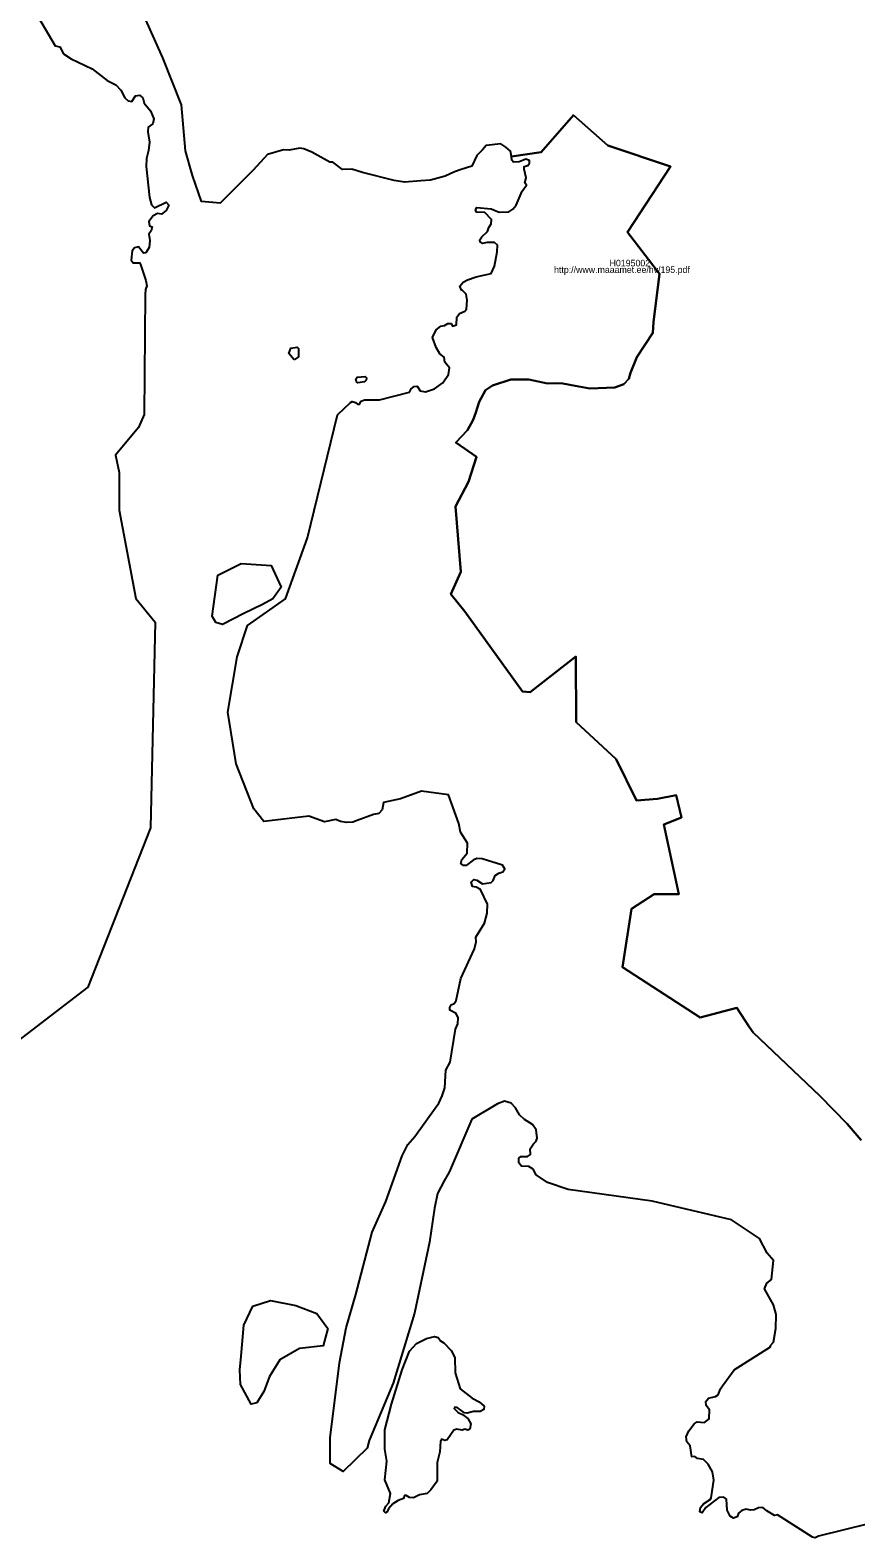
# Model space of a CAD drawing. Extents: x 369010 to 739155, y 6377141 to 6634081.
# Drawn here: x 473944 to 477086, y 6488350 to 6494090 of the extents above; entities that cross this region are included whole.
import ezdxf

# ---------------------------------------------------------------- set-up
doc = ezdxf.new("R2010")
doc.units = 0
for name, color, linetype in [('H_LINK', 7, 'Continuous'), ('H_PIIR', 7, 'Continuous'), ('H_TUNNUS', 7, 'Continuous')]:
    doc.layers.add(name, color=color, linetype=linetype)

msp = doc.modelspace()

# ---------------------------------------------------------------- linework, layer by layer
at = {"layer": 'H_PIIR'}
for points in [[(477105.81, 6489863.6599), (477053.1001, 6489926.8), (476948.82, 6490032.56), (476694.89, 6490274.23), (476679.33, 6490296.0501), (476633.0701, 6490367.9899), (476493.14, 6490331.6599), (476197.2999, 6490523.06), (476232.4499, 6490745.25), (476318.77, 6490800.43), (476411.3899, 6490800.8701), (476354.3301, 6491066.2601), (476422.4101, 6491092.2401), (476402.1901, 6491177.4999), (476330.5199, 6491164.3401), (476250.9799, 6491157.16), (476173.7901, 6491315.3599), (476021.6, 6491455.23), (476019.83, 6491706.0699), (475846.6001, 6491569.67), (475816.77, 6491572.98), (475597.3201, 6491877.66), (475544.2301, 6491943.1199), (475582.14, 6492027.4901), (475562.5499, 6492276.2201), (475611.42, 6492370.95), (475641.97, 6492465.69), (475563.7999, 6492520.34), (475608.2199, 6492567.65), (475629.13, 6492607.3199), (475639.8599, 6492634.9099), (475652.7401, 6492675.06), (475675.8301, 6492719.44), (475702.7499, 6492737.89), (475772.24, 6492760.48), (475840.7099, 6492760.48), (475911.8301, 6492745.3401), (475942.09, 6492746.7), (475970.38, 6492745.6), (476017.03, 6492736.4899), (476073.5, 6492725.46), (476168.17, 6492729.35), (476202.22, 6492741.94), (476221.6101, 6492763.0399), (476227.5, 6492786.31), (476252.8101, 6492845.74), (476312.6699, 6492937.3801), (476314.9799, 6492979.1), (476337.83, 6493162.4601), (476216.68, 6493321.0601), (476380.2801, 6493571.28), (476142.0301, 6493650.73), (476010.69, 6493766.86), (475888.52, 6493626.2901), (475774.6921, 6493608.7703), (475770.8299, 6493629.36), (475753.4, 6493645.4001), (475735.2701, 6493657.25), (475679.35, 6493651.66), (475664.3384, 6493634.0993), (475643.4809, 6493612.6467), (475624.6508, 6493572.1867), (475583.5938, 6493559.8427), (475558.7, 6493551.03), (475522.9239, 6493534.0326), (475467.488, 6493519.7991), (475430.1431, 6493516.6715), (475367.4753, 6493511.8616), (475328.4685, 6493517.8132), (475208.725, 6493548.3742), (475168.275, 6493560.9243), (475132.715, 6493560.2243), (475095.04, 6493587.5199), (475084.58, 6493588.2201), (475014.84, 6493625.88), (474984.86, 6493638.4401), (474969.5201, 6493641.2199), (474929.0699, 6493633.55), (474908.15, 6493634.2499), (474846.5742, 6493616.982), (474792.3345, 6493557.4507), (474666.6572, 6493431.7733), (474595.2195, 6493438.3879), (474560.8236, 6493537.6069), (474534.3653, 6493631.5341), (474519.8131, 6493806.1595), (474448.3755, 6493984.7536), (474357.0941, 6494189.8061)], [(473975.961, 6494138.2034), (474038.8399, 6494030.7401), (474056.7601, 6494027.2699), (474070.6301, 6494000.6699), (474100.1101, 6493981.0199), (474180, 6493943.16), (474237.2199, 6493898.0701), (474269.5899, 6493882.4601), (474288.0899, 6493862.2299), (474303.6901, 6493832.7399), (474316.4101, 6493821.7599), (474330.2801, 6493818.8699), (474344.1601, 6493840.8399), (474359.1801, 6493842.5699), (474371.9, 6493832.7399), (474377.68, 6493812.51), (474401.38, 6493783.03), (474414.67, 6493752.39), (474410.05, 6493733.31), (474393.29, 6493721.17), (474391.55, 6493702.68), (474397.91, 6493663.36), (474394.3801, 6493632.5199), (474385.7001, 6493601.31), (474385.1301, 6493570.67), (474397.8401, 6493453.32), (474404.78, 6493425.5701), (474417.2399, 6493413.53), (474461.2001, 6493436.07), (474471.1001, 6493423.6299), (474460.5699, 6493404.0399), (474443.2899, 6493390.13), (474428.2599, 6493391.71), (474411.4599, 6493383.64), (474395.4301, 6493361.3299), (474397.52, 6493345.98), (474407.28, 6493341.7999), (474404.49, 6493326.46), (474394.7299, 6493313.9), (474399.61, 6493289.49), (474396.12, 6493262.2901), (474383.57, 6493242.77), (474374.51, 6493241.3699), (474355.6801, 6493265.0799), (474340.34, 6493261.5999), (474331.2699, 6493250.44), (474327.78, 6493214.8699), (474336.15, 6493205.1101), (474360.56, 6493205.1101), (474364.7399, 6493193.95), (474383.57, 6493137.24), (474387.76, 6493117.02), (474382.88, 6493103.0701), (474381.7681, 6493083.5003), (474377.5347, 6492627.3577), (474355.3097, 6492577.616), (474268.5262, 6492472.3116), (474281.7554, 6492406.1656), (474281.7554, 6492263.2903), (474345.917, 6491925.9459), (474418.6775, 6491836.6489), (474401.2796, 6491053.1556), (474163.1541, 6490447.2585), (473790.0908, 6490161.508)], [(477231.0565, 6488427.7208), (476942.98, 6488357.15), (476931.13, 6488350.18), (476920.67, 6488352.96), (476787.84, 6488437.3699), (476776.6801, 6488435.2801), (476747.4, 6488452.71), (476732.06, 6488465.96), (476714.62, 6488463.87), (476698.58, 6488456.9), (476684.64, 6488455.5), (476667.9, 6488459.69), (476651.16, 6488454.1099), (476639.3101, 6488444.3399), (476634.43, 6488430.4), (476619.7801, 6488425.52), (476607.23, 6488432.49), (476595.3799, 6488455.5), (476593.98, 6488498.0499), (476582.8201, 6488505.0201), (476564.7, 6488503.63), (476515.1799, 6488465.2701), (476500.54, 6488445.74), (476491.47, 6488449.23), (476494.9599, 6488465.2701), (476505.4199, 6488479.91), (476531.22, 6488495.95), (476535.4099, 6488502.93), (476545.1699, 6488569.88), (476540.29, 6488601.2599), (476524.25, 6488631.2499), (476506.1201, 6488647.9899), (476483.11, 6488652.1801), (476473.34, 6488659.85), (476461.4899, 6488658.4499), (476454.52, 6488701), (476442.6601, 6488716.34), (476439.87, 6488734.47), (476449.63, 6488758.1799), (476470.55, 6488783.99), (476481.7099, 6488792.3601), (476510.3, 6488788.8701), (476527.04, 6488802.8201), (476528.4299, 6488836.99), (476515.8801, 6488854.43), (476514.49, 6488869.0701), (476524.9499, 6488882.3199), (476552.1399, 6488887.9), (476561.21, 6488894.88), (476570.27, 6488917.89), (476578.6399, 6488929.0499), (476622.7493, 6488990.1939), (476761.24, 6489077.07), (476759.8399, 6489081.25), (476772.39, 6489095.1999), (476780.7601, 6489146.81), (476782.8499, 6489200.51), (476772.39, 6489237.48), (476737.53, 6489298.8499), (476747.2901, 6489319.7701), (476764.72, 6489333.72), (476772.2056, 6489405.8832), (476748.1621, 6489434.5361), (476719.0578, 6489490.0987), (476611.9014, 6489560.7426), (476310.2758, 6489632.1802), (475991.1876, 6489676.6303), (475911.8125, 6489703.6179), (475869.5599, 6489732.8101), (475857.71, 6489753.73), (475841.67, 6489764.2), (475813.78, 6489765.5899), (475802.6199, 6489778.14), (475802.6199, 6489796.2801), (475810.99, 6489801.86), (475836.0899, 6489802.5499), (475847.25, 6489809.5299), (475846.5501, 6489831.15), (475858.41, 6489850.68), (475869.5599, 6489860.44), (475873.0499, 6489872.3), (475868.87, 6489903.6801), (475855.62, 6489923.9001), (475824.93, 6489943.4301), (475806.1099, 6489960.87), (475790.76, 6489987.3701), (475774.03, 6490005.5), (475748.23, 6490012.48), (475722.4299, 6490002.7099), (475624.8, 6489944.13), (475538.2201, 6489742.1589), (475518.49, 6489709.98), (475493.77, 6489661.1962), (475482.6574, 6489605.6336), (475463.6074, 6489475.4584), (475406.4573, 6489205.5828), (475324.68, 6488939.59), (475233.5197, 6488721.3317), (475225.8497, 6488691.3417), (475134.9942, 6488602.5962), (475085.7816, 6488632.7588), (475085.7816, 6488731.184), (475120.7067, 6489016.9345), (475146.1068, 6489150.2848), (475182.6193, 6489277.2851), (475244.532, 6489513.5585), (475296.9196, 6489631.0337), (475358.8, 6489804.8299), (475380.4201, 6489848.07), (475407.61, 6489878.7599), (475485.02, 6489986.1601), (475498.83, 6490005.0499), (475511.3801, 6490032.9501), (475521.1401, 6490063.64), (475525.33, 6490130.59), (475542.06, 6490161.28), (475562.29, 6490286.8101), (475571.3501, 6490307.04), (475572.05, 6490330.0501), (475565.0801, 6490346.0899), (475540.6699, 6490359.3399), (475539.97, 6490369.8001), (475546.25, 6490378.87), (475557.4099, 6490384.45), (475565.0801, 6490395.61), (475582.51, 6490480.0001), (475634.1099, 6490592.28), (475640.39, 6490618.78), (475639, 6490637.6101), (475672.98, 6490690.6601), (475682.0399, 6490728.32), (475683.44, 6490763.1899), (475657.64, 6490818.28), (475640.9, 6490827.3501), (475626.95, 6490830.1399), (475622.0699, 6490846.8799), (475631.8299, 6490856.64), (475642.99, 6490853.8499), (475664.61, 6490840.5999), (475697.38, 6490845.48), (475705.7501, 6490852.46), (475713.42, 6490871.2901), (475726.67, 6490880.3599), (475742.7101, 6490885.93), (475749.6801, 6490897.7901), (475741.32, 6490911.0401), (475663.91, 6490935.45), (475642.99, 6490936.8499), (475629.74, 6490930.5699), (475603.24, 6490909.65), (475592.0801, 6490909.65), (475583.02, 6490918.0201), (475586.51, 6490932.66), (475606.73, 6490957.0699), (475607.43, 6490994.7301), (475581.7882, 6491036.415), (475575.4382, 6491069.7525), (475535.7506, 6491179.2903), (475432.5202, 6491193.0773), (475353.1877, 6491163.4152), (475287.8999, 6491149.9001), (475283.72, 6491121.31), (475270.47, 6491108.06), (475250.25, 6491104.57), (475188.1899, 6491081.56), (475171.4499, 6491074.58), (475147.7399, 6491073.1901), (475124.0299, 6491078.07), (475107.2999, 6491085.7399), (475064.2622, 6491076.1026), (475003.937, 6491098.3276), (474832.4867, 6491077.6901), (474794.3866, 6491125.3151), (474727.7115, 6491296.7655), (474695.9614, 6491493.6159), (474730.8865, 6491704.7538), (474770.5741, 6491823.8165), (474915.0369, 6491925.4167), (474999.1745, 6492157.1922), (475113.4748, 6492625.5056), (475162.3301, 6492672.4699), (475168.6101, 6492676.6601), (475181.8601, 6492672.4699), (475189.53, 6492666.2001), (475196.5, 6492666.89), (475203.48, 6492677.36), (475215.3301, 6492682.9401), (475272.5101, 6492682.9401), (475386.87, 6492711.53), (475393.15, 6492724.78), (475404.31, 6492733.1501), (475416.1601, 6492735.24), (475427.32, 6492717.11), (475447.54, 6492713.62), (475482.4099, 6492724.78), (475513.79, 6492747.1), (475535.41, 6492779.8801), (475538.8899, 6492804.98), (475521.46, 6492826.6001), (475519.3699, 6492845.43), (475501.93, 6492857.99), (475487.99, 6492881.7), (475474.74, 6492920.0601), (475488.6799, 6492949.35), (475506.1201, 6492963.2999), (475520.76, 6492966.0899), (475532.6199, 6492973.0599), (475545.17, 6492973.0599), (475550.75, 6492964.0001), (475565.39, 6492968.18), (475567.48, 6492998.17), (475577.94, 6493011.42), (475597.47, 6493020.4901), (475603.7401, 6493028.16), (475606.5301, 6493062.33), (475602.3499, 6493084.65), (475588.47, 6493098.53), (475584.92, 6493099.9899), (475578.64, 6493115.34), (475591.89, 6493130.6801), (475608.3501, 6493139.7699), (475641.1199, 6493151.62), (475697.6099, 6493163.4799), (475710.8599, 6493191.38), (475720.62, 6493246.47), (475722.0201, 6493271.58), (475710.8599, 6493281.3401), (475682.97, 6493281.3401), (475665.53, 6493277.8601), (475656.47, 6493282.74), (475655.0701, 6493292.5), (475662.74, 6493303.6599), (475684.3599, 6493323.19), (475688.5401, 6493339.23), (475697.6099, 6493353.18), (475699.7, 6493369.22), (475673.2, 6493396.42), (475641.8201, 6493397.1199), (475638.3401, 6493406.88), (475643.22, 6493415.25), (475697.6099, 6493410.3699), (475728.2901, 6493397.8101), (475764.5499, 6493399.21), (475779.9, 6493408.2801), (475793.14, 6493424.3199), (475815.4601, 6493477.3199), (475832.2001, 6493499.64), (475826.62, 6493509.4), (475830.8, 6493528.2301), (475823.13, 6493561.7101), (475823.83, 6493570.7699), (475837.08, 6493575.66), (475844.05, 6493583.33), (475843.35, 6493593.79), (475829.41, 6493598.6701), (475804.2999, 6493589.6), (475783.38, 6493587.5099), (475777.11, 6493595.88), (475774.6921, 6493608.7703), (475888.52, 6493626.2901), (476010.69, 6493766.86), (476142.0301, 6493650.73), (476380.2801, 6493571.28), (476216.68, 6493321.0601), (476337.83, 6493162.4601), (476314.9799, 6492979.1), (476312.6699, 6492937.3801), (476252.8101, 6492845.74), (476227.5, 6492786.31), (476221.6101, 6492763.0399), (476202.22, 6492741.94), (476168.17, 6492729.35), (476073.5, 6492725.46), (476017.03, 6492736.4899), (475970.38, 6492745.6), (475942.09, 6492746.7), (475911.8301, 6492745.3401), (475840.7099, 6492760.48), (475772.24, 6492760.48), (475702.7499, 6492737.89), (475675.8301, 6492719.44), (475652.7401, 6492675.06), (475639.8599, 6492634.9099), (475629.13, 6492607.3199), (475608.2199, 6492567.65), (475563.7999, 6492520.34), (475641.97, 6492465.69), (475611.42, 6492370.95), (475562.5499, 6492276.2201), (475582.14, 6492027.4901), (475544.2301, 6491943.1199), (475597.3201, 6491877.66), (475816.77, 6491572.98), (475846.6001, 6491569.67), (476019.83, 6491706.0699), (476021.6, 6491455.23), (476173.7901, 6491315.3599), (476250.9799, 6491157.16), (476330.5199, 6491164.3401), (476402.1901, 6491177.4999), (476422.4101, 6491092.2401), (476354.3301, 6491066.2601), (476411.3899, 6490800.8701), (476318.77, 6490800.43), (476232.4499, 6490745.25), (476197.2999, 6490523.06), (476493.14, 6490331.6599), (476633.0701, 6490367.9899), (476679.33, 6490296.0501), (476694.89, 6490274.23), (476948.82, 6490032.56), (477053.1001, 6489926.8), (477105.81, 6489863.6599)]]:
    msp.add_lwpolyline(points, dxfattribs=at)
for points in [[(474948.3744, 6492835.5852), (474927.7369, 6492859.3978), (474935.6744, 6492880.0353), (474959.487, 6492883.2103), (474964.2495, 6492878.4478), (474964.2495, 6492846.6978)], [(475202.74, 6492770.78), (475218.8701, 6492771.89), (475224.0101, 6492766.98), (475222.1399, 6492757.8599), (475215.3601, 6492752.01), (475190.11, 6492747.8), (475185.1999, 6492751.0701), (475183.33, 6492761.3699), (475187.5399, 6492769.79)], [(474635.6363, 6491858.7416), (474657.8613, 6492015.9044), (474746.7615, 6492060.3545), (474861.0618, 6492052.417), (474899.1618, 6491969.8668), (474867.4118, 6491925.4167), (474827.7242, 6491903.1917), (474756.2865, 6491869.8541), (474675.3239, 6491826.9916), (474649.9238, 6491834.9291)], [(474746.056, 6489042.07), (474757.1685, 6489159.5452), (474790.5061, 6489232.5704), (474858.7687, 6489253.2079), (474954.0189, 6489234.1579), (475034.9815, 6489203.9953), (475076.2566, 6489146.8452), (475058.7941, 6489081.7576), (474968.3064, 6489070.6451), (474893.6938, 6489027.7825), (474854.0062, 6488964.2824), (474833.3686, 6488907.1322), (474806.3811, 6488864.2697), (474784.156, 6488859.5071), (474744.4685, 6488934.1198), (474741.2935, 6488989.6824)], [(475517.43, 6489092.73), (475546.22, 6489063.94), (475560, 6489036.3799), (475560.62, 6488978.1201), (475580.0401, 6488917.98), (475625.14, 6488881.6499), (475652.7001, 6488867.8699), (475670.86, 6488851.58), (475669.61, 6488839.0499), (475655.83, 6488830.9099), (475630.7701, 6488831.5399), (475606.35, 6488824.6401), (475596.32, 6488826.52), (475568.14, 6488846.5701), (475559.37, 6488847.2001), (475556.8599, 6488842.81), (475571.9001, 6488827.78), (475588.81, 6488820.26), (475608.8501, 6488804.6), (475620.75, 6488783.93), (475616.9901, 6488764.5099), (475608.8501, 6488760.75), (475598.2, 6488764.5099), (475586.9301, 6488760.1201), (475566.89, 6488764.5099), (475555.6099, 6488760.1201), (475529.93, 6488723.79), (475521.7901, 6488721.2799), (475509.26, 6488726.3), (475505.4999, 6488718.78), (475502.37, 6488677.4399), (475492.98, 6488636.72), (475492.98, 6488565.93), (475468.5499, 6488532.7301), (475454.1399, 6488518.9501), (475424.6999, 6488514.56), (475402.7799, 6488502.0399), (475386.5, 6488503.2901), (475374.6001, 6488511.4301), (475367.7101, 6488511.4301), (475363.95, 6488500.16), (475344.5399, 6488492.67), (475323.8701, 6488479.5199), (475306.9599, 6488460.73), (475301.9401, 6488448.82), (475295.68, 6488445.0701), (475289.42, 6488451.9601), (475297.56, 6488470.75), (475308.2101, 6488483.9), (475314.4699, 6488518.98), (475293.8001, 6488570.98), (475301.3201, 6488642.3901), (475293.8001, 6488687.49), (475293.8001, 6488762.04), (475318.23, 6488859.13), (475359.5701, 6488989.43), (475386.5, 6489060.84), (475413.44, 6489089.66), (475452.26, 6489109.0399), (475481.69, 6489117.1801), (475496.73, 6489113.42), (475504.8699, 6489099.64)]]:
    msp.add_lwpolyline(points, close=True, dxfattribs=at)

# ---------------------------------------------------------------- texts
at = {"layer": 'H_LINK'}
msp.add_text('http://www.maaamet.ee/hv/195.pdf', height=25, rotation=0, dxfattribs=at).set_placement((475937.2982, 6493166.0361))
at = {"layer": 'H_TUNNUS'}
msp.add_text('H0195002', height=25, rotation=0, dxfattribs=at).set_placement((476148.5272, 6493191.0361))

doc.saveas('drawing.dxf')
